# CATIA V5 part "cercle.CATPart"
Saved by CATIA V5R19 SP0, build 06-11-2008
Part number: Part3
Bounding box of the stored display mesh (mm): x -35 to 35, y 0 to 0, z -34.808 to 34.808
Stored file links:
  F:\20\cercle.CATPart
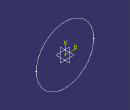
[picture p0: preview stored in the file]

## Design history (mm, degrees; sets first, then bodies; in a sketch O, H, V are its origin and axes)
Body1 (main body)
  Sketch1 on zx-plane, origin (0, 0, 0), H (-1, 0, 0), V (0, 0, 1)
    circle A1 centre (0, 0) radius 35
    radius A1 = 35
